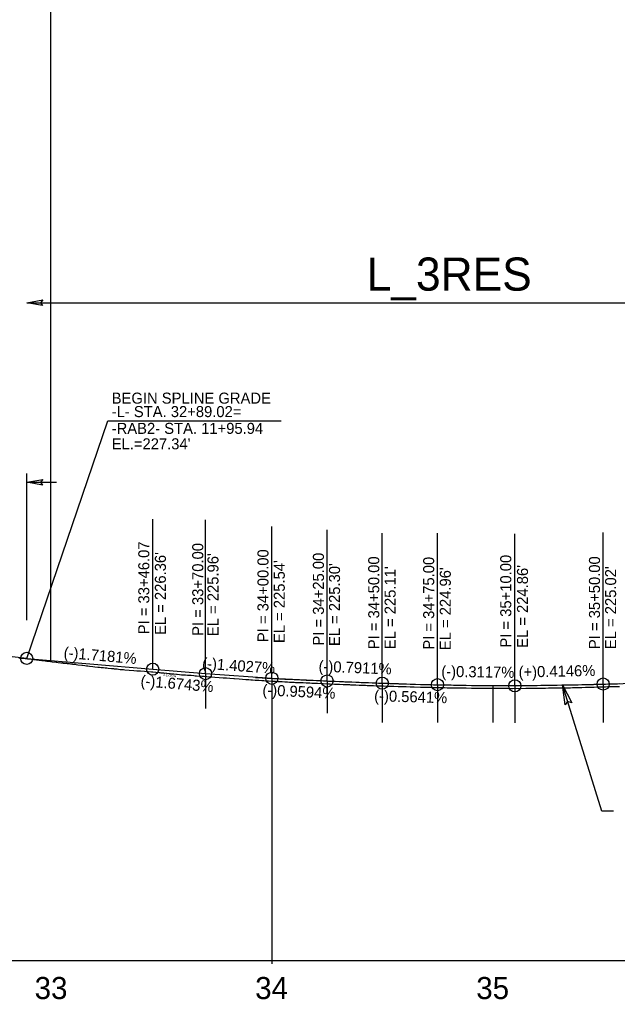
# Model space of a CAD drawing. Extents: x 2115752 to 2121174, y 562881 to 567245.
# Drawn here: x 2118982.1 to 2119252.8, y 566358.2 to 566801.7 of the extents above; entities that cross this region are included whole.
import ezdxf

# ---------------------------------------------------------------- set-up
doc = ezdxf.new("R2010")
doc.units = 0
for name, color, linetype in [('Exist Profile Cell', 7, 'Continuous'), ('Exist Vertical Profile Ground Line', 7, 'Continuous'), ('Exist Vertical Profile Horizontal Axis Label Major', 7, 'Continuous'), ('Prop Terminator CELL', 7, 'Continuous'), ('Prop Vertical Profile Grade', 7, 'Continuous'), ('Prop Vertical Profile Grade Label', 7, 'Continuous'), ('Prop VPI Label', 7, 'Continuous'), ('Scratch_Level_1', 7, 'Continuous')]:
    doc.layers.add(name, color=color, linetype=linetype)

msp = doc.modelspace()

# ---------------------------------------------------------------- linework, layer by layer
at = {"layer": 'Exist Profile Cell'}
msp.add_line((2116696.3, 566375.81), (2121174.42, 566375.81), dxfattribs=at)
at = {"layer": 'Exist Vertical Profile Ground Line'}
for points in [[(2118981.81, 566512.81), (2118982.8, 566512.69), (2118983.58, 566512.6), (2118985.71, 566512.32), (2118987.44, 566512.13), (2118988.58, 566512), (2118989.01, 566511.95), (2118989.75, 566511.87), (2118992.13, 566511.6), (2118992.91, 566511.51), (2118994.39, 566511.32), (2118995.37, 566511.2), (2118996.03, 566511.13), (2118996.87, 566511.01), (2118998.63, 566510.81), (2118999.03, 566510.77), (2118999.56, 566510.72), (2119000.8, 566510.55), (2119001.4, 566510.48), (2119001.88, 566510.42), (2119003.15, 566510.29), (2119003.67, 566510.22), (2119005.12, 566510.04), (2119005.99, 566509.95), (2119006.75, 566509.87), (2119008.48, 566509.64), (2119010.25, 566509.46), (2119010.63, 566509.41), (2119011.65, 566509.28), (2119012.46, 566509.19), (2119012.95, 566509.14), (2119013.77, 566509.05), (2119015.27, 566508.88), (2119016.22, 566508.77), (2119017.59, 566508.62), (2119018.3, 566508.54), (2119019.09, 566508.46), (2119020.05, 566508.35), (2119020.92, 566508.26), (2119021.65, 566508.18), (2119022.23, 566508.12), (2119023.76, 566507.96), (2119024.55, 566507.88), (2119024.98, 566507.83), (2119026.21, 566507.73), (2119026.87, 566507.64), (2119027.58, 566507.56), (2119027.94, 566507.52), (2119028.28, 566507.49), (2119029.19, 566507.43), (2119029.7, 566507.4), (2119031.71, 566507.18), (2119033.83, 566507.02), (2119035.12, 566506.93), (2119036.78, 566506.87), (2119038.69, 566506.67), (2119040.37, 566506.57), (2119041.83, 566506.42), (2119042.4, 566506.37), (2119043.85, 566506.27), (2119045.25, 566506.13), (2119045.63, 566506.11), (2119046.06, 566506.06), (2119047.45, 566505.97), (2119048.64, 566505.84), (2119049.82, 566505.72), (2119050.92, 566505.6), (2119051.98, 566505.48), (2119053.45, 566505.33), (2119054.47, 566505.22), (2119055.43, 566505.15), (2119056.27, 566505.11), (2119057.2, 566505.01), (2119058.09, 566504.93), (2119058.82, 566504.9), (2119059.84, 566504.86), (2119060.94, 566504.75), (2119061.6, 566504.69), (2119062.16, 566504.66), (2119064.56, 566504.49), (2119064.97, 566504.46), (2119065.61, 566504.41), (2119066.86, 566504.34), (2119068.24, 566504.21), (2119068.98, 566504.14), (2119070.44, 566504.05), (2119072.44, 566503.9), (2119074.27, 566503.73), (2119075.8, 566503.65), (2119077.25, 566503.51), (2119079.1, 566503.42), (2119079.41, 566503.4), (2119081.57, 566503.23), (2119083.05, 566503.14), (2119084.51, 566503.02), (2119085.92, 566502.93), (2119086.75, 566502.87), (2119087.51, 566502.79), (2119088.83, 566502.69)], [(2119088.83, 566502.69), (2119089.33, 566502.67), (2119089.88, 566502.64), (2119090.48, 566502.6), (2119091.81, 566502.49), (2119092.72, 566502.45), (2119093.42, 566502.4), (2119094.2, 566502.37), (2119094.83, 566502.33), (2119096.12, 566502.28), (2119096.96, 566502.22), (2119097.89, 566502.18), (2119099.1, 566502.1), (2119099.71, 566502.05), (2119101.05, 566502), (2119102.14, 566501.94), (2119103.37, 566501.88), (2119104.37, 566501.81), (2119105.22, 566501.8), (2119106.37, 566501.74), (2119107.07, 566501.68), (2119108.49, 566501.66), (2119109.36, 566501.62), (2119110.46, 566501.57), (2119111.81, 566501.47), (2119112.52, 566501.47), (2119113.55, 566501.43), (2119114.45, 566501.37), (2119116.5, 566501.31), (2119117.05, 566501.26), (2119119.57, 566501.15), (2119121.91, 566501.04), (2119122.74, 566501.01), (2119124.67, 566500.93), (2119126.92, 566500.83), (2119128.64, 566500.76), (2119129.34, 566500.72), (2119129.72, 566500.71), (2119131.46, 566500.64), (2119131.94, 566500.62), (2119132.54, 566500.6), (2119134.3, 566500.52), (2119135.83, 566500.47), (2119136.72, 566500.43), (2119137.13, 566500.41), (2119138.73, 566500.34), (2119139.39, 566500.31), (2119139.99, 566500.29), (2119141.63, 566500.23), (2119142.34, 566500.21), (2119143.57, 566500.17), (2119144.49, 566500.13), (2119146.08, 566500.09), (2119146.53, 566500.07), (2119146.9, 566500.06), (2119148.63, 566500), (2119149.72, 566499.97), (2119150.34, 566499.95), (2119151.53, 566499.9), (2119153.45, 566499.84), (2119153.75, 566499.83), (2119155.93, 566499.75), (2119157.19, 566499.73), (2119158.86, 566499.67), (2119160.4, 566499.62), (2119160.79, 566499.61), (2119163.65, 566499.53), (2119164.12, 566499.52), (2119164.5, 566499.51), (2119167.36, 566499.45), (2119168.22, 566499.43), (2119169.55, 566499.38), (2119170.7, 566499.37), (2119171.3, 566499.36), (2119171.96, 566499.35), (2119173.08, 566499.32), (2119174.08, 566499.31), (2119174.51, 566499.3), (2119175.68, 566499.27), (2119177.46, 566499.24), (2119178.49, 566499.23), (2119179.34, 566499.22), (2119180.13, 566499.19), (2119180.85, 566499.18), (2119181.67, 566499.17), (2119183.06, 566499.15), (2119184.23, 566499.13), (2119186.72, 566499.07), (2119187.59, 566499.05), (2119188.97, 566499.05), (2119190.38, 566499.03), (2119190.99, 566499.03), (2119192.53, 566499.05), (2119194.1, 566499.01), (2119194.43, 566499), (2119196.05, 566499), (2119197.82, 566498.98), (2119198.38, 566498.99), (2119199.59, 566499.02), (2119201.58, 566498.99), (2119203.14, 566499)], [(2119203.14, 566499), (2119204.77, 566498.97), (2119205.29, 566498.96), (2119206.66, 566498.98), (2119207.98, 566498.96), (2119208.54, 566498.97), (2119209.01, 566498.96), (2119211.33, 566498.98), (2119211.97, 566499), (2119212.71, 566499.01), (2119214.66, 566499.02), (2119215.51, 566499.03), (2119216.41, 566499.05), (2119218.15, 566499.09), (2119219.07, 566499.09), (2119220.14, 566499.12), (2119221.49, 566499.14), (2119222.56, 566499.15), (2119223.93, 566499.18), (2119224.44, 566499.19), (2119224.85, 566499.2), (2119225.57, 566499.21), (2119227.55, 566499.25), (2119227.9, 566499.25), (2119228.2, 566499.25), (2119231.15, 566499.26), (2119231.59, 566499.27), (2119232.36, 566499.29), (2119233.27, 566499.31), (2119234.96, 566499.36), (2119236.7, 566499.4), (2119238.31, 566499.43), (2119238.84, 566499.44), (2119239.16, 566499.45), (2119241.98, 566499.53), (2119242.29, 566499.54), (2119243.87, 566499.58), (2119245.11, 566499.62), (2119246.17, 566499.66), (2119247.34, 566499.68), (2119248.48, 566499.73), (2119250.02, 566499.77), (2119251.76, 566499.81), (2119252.75, 566499.83), (2119253.65, 566499.85)]]:
    msp.add_lwpolyline(points, dxfattribs=at)
at = {"layer": 'Prop Terminator CELL'}
for points in [[(2118992.52, 566591.01), (2118985.32, 566592.25), (2118992.56, 566593.53), (2118991.64, 566592.25)], [(2119229.06, 566491.47), (2119227.85, 566500.53), (2119232.08, 566492.37), (2119230.21, 566492.99)]]:
    msp.add_lwpolyline(points, close=True, dxfattribs=at)
at = {"layer": 'Prop Vertical Profile Grade'}
msp.add_lwpolyline([(2118985.32, 566512.53), (2119042.37, 566507.63), (2119066.3, 566505.62), (2119096.3, 566503.52), (2119121.3, 566502.32), (2119146.3, 566501.33), (2119171.3, 566500.63), (2119206.3, 566500.08), (2119246.3, 566500.91), (2119296.3, 566502.56), (2119321.3, 566503.63), (2119356.3, 566505.99)], dxfattribs=at)
at = {"layer": 'Prop VPI Label'}
for p, q in [((2118985.32, 566512.53), (2119022.04, 566620.13)), ((2119022.04, 566620.13), (2119100.59, 566620.13)), ((2118985.32, 566529.85), (2118985.32, 566596.16)), ((2118985.32, 566592.25), (2118998.8, 566592.25)), ((2119042.37, 566507.63), (2119042.37, 566575.61)), ((2119066.3, 566505.62), (2119066.3, 566575.18)), ((2119096.3, 566503.52), (2119096.3, 566572.16)), ((2119121.3, 566502.32), (2119121.3, 566570.65)), ((2119146.3, 566501.33), (2119146.3, 566569.14)), ((2119171.3, 566500.63), (2119171.3, 566569.14)), ((2119206.3, 566500.08), (2119206.3, 566568.92)), ((2119246.3, 566500.91), (2119246.3, 566569.53)), ((2118985.32, 566512.53), (2118966.65, 566514.53))]:
    msp.add_line(p, q, dxfattribs=at)
msp.add_lwpolyline([(2119251.04, 566443.36), (2119245.74, 566443.36), (2119227.85, 566500.53)], dxfattribs=at)
for centre in [(2118985.32, 566512.53), (2119042.37, 566507.63), (2119066.3, 566505.62), (2119096.3, 566503.52), (2119121.3, 566502.32), (2119146.3, 566501.33), (2119171.3, 566500.63), (2119246.3, 566500.91), (2119206.3, 566500.08)]:
    msp.add_circle(centre, 2.75, dxfattribs=at)
at = {"layer": 'Scratch_Level_1'}
for p, q in [((2118996.3, 566511.09), (2118996.3, 567245.2)), ((2118985.32, 566673.51), (2119356.3, 566673.51)), ((2118985.32, 566512.38), (2118985.32, 566512.53)), ((2118985.32, 566512.53), (2118996.3, 566511.09)), ((2119047.45, 566505.97), (2119054.47, 566505.22)), ((2119066.3, 566505.62), (2119066.3, 566489.88)), ((2119096.3, 566503.52), (2119096.3, 566374.25)), ((2119121.3, 566502.32), (2119121.3, 566487.77)), ((2119146.3, 566501.33), (2119146.3, 566483.58)), ((2119171.3, 566500.63), (2119171.3, 566483.58)), ((2119196.3, 566500.25), (2119196.3, 566483.55)), ((2119206.3, 566500.22), (2119206.3, 566483.37)), ((2119246.3, 566500.91), (2119246.3, 566483.58))]:
    msp.add_line(p, q, dxfattribs=at)
msp.add_lwpolyline([(2118992.52, 566672.27), (2118985.32, 566673.51), (2118992.56, 566674.79), (2118991.64, 566673.51)], close=True, dxfattribs=at)
for points in [[(2119000.34, 566510.61), (2119007.79, 566509.97)], [(2119088.88, 566503.94), (2119089.4, 566503.92), (2119089.96, 566503.88), (2119090.57, 566503.85), (2119091.9, 566503.74), (2119092.79, 566503.69), (2119093.48, 566503.65), (2119094.26, 566503.62), (2119094.89, 566503.58), (2119096.19, 566503.53), (2119097.03, 566503.47), (2119097.96, 566503.42), (2119099.19, 566503.35), (2119099.78, 566503.3), (2119101.11, 566503.25), (2119102.2, 566503.18), (2119103.44, 566503.13), (2119104.42, 566503.06), (2119105.26, 566503.05), (2119106.46, 566502.99), (2119107.14, 566502.93), (2119108.53, 566502.91), (2119109.42, 566502.87), (2119110.53, 566502.81), (2119111.85, 566502.72), (2119112.54, 566502.73), (2119113.62, 566502.68), (2119114.51, 566502.62), (2119116.57, 566502.56), (2119117.14, 566502.51), (2119119.63, 566502.4), (2119121.96, 566502.29), (2119122.79, 566502.26), (2119124.73, 566502.18), (2119126.98, 566502.07), (2119128.69, 566502.01), (2119129.4, 566501.97), (2119129.77, 566501.96), (2119131.5, 566501.89), (2119132, 566501.87), (2119132.59, 566501.85), (2119134.35, 566501.77), (2119135.88, 566501.72), (2119136.78, 566501.68), (2119137.18, 566501.66), (2119138.79, 566501.59), (2119139.44, 566501.56), (2119140.04, 566501.54), (2119141.67, 566501.48), (2119142.38, 566501.46), (2119143.61, 566501.42), (2119144.54, 566501.38), (2119146.12, 566501.34), (2119146.57, 566501.32), (2119146.94, 566501.31), (2119148.67, 566501.25), (2119149.76, 566501.22), (2119150.39, 566501.2), (2119151.58, 566501.15), (2119153.49, 566501.09), (2119153.79, 566501.08), (2119155.96, 566501), (2119157.22, 566500.98), (2119158.9, 566500.92), (2119160.44, 566500.87), (2119160.83, 566500.85), (2119163.68, 566500.78), (2119164.16, 566500.77), (2119164.54, 566500.76), (2119167.39, 566500.7), (2119168.26, 566500.68), (2119169.57, 566500.63), (2119170.72, 566500.62), (2119171.32, 566500.61), (2119171.99, 566500.6), (2119173.11, 566500.57), (2119174.1, 566500.56), (2119174.53, 566500.55), (2119175.71, 566500.52), (2119177.47, 566500.49), (2119178.51, 566500.48), (2119179.37, 566500.47), (2119180.16, 566500.44), (2119180.87, 566500.43), (2119181.69, 566500.42), (2119183.08, 566500.4), (2119184.26, 566500.38), (2119186.75, 566500.32), (2119187.6, 566500.3), (2119188.98, 566500.3), (2119190.39, 566500.28), (2119190.99, 566500.28), (2119192.54, 566500.3), (2119194.12, 566500.26), (2119194.43, 566500.25), (2119196.06, 566500.25), (2119197.82, 566500.23), (2119198.35, 566500.24), (2119199.58, 566500.27), (2119201.58, 566500.24), (2119203.14, 566500.25)], [(2119203.16, 566500.25), (2119204.79, 566500.22), (2119205.29, 566500.21), (2119206.66, 566500.23), (2119207.98, 566500.21), (2119208.54, 566500.22), (2119209.02, 566500.21), (2119211.31, 566500.23), (2119211.95, 566500.25), (2119212.7, 566500.26), (2119214.65, 566500.27), (2119215.49, 566500.28), (2119216.39, 566500.3), (2119218.14, 566500.34), (2119219.05, 566500.34), (2119220.12, 566500.37), (2119221.47, 566500.39), (2119222.54, 566500.4), (2119223.91, 566500.43), (2119224.42, 566500.44), (2119224.83, 566500.45), (2119225.54, 566500.46), (2119227.53, 566500.5), (2119227.88, 566500.5), (2119228.2, 566500.5), (2119231.14, 566500.51), (2119231.56, 566500.52), (2119232.34, 566500.54), (2119233.24, 566500.56), (2119234.92, 566500.61), (2119236.67, 566500.65), (2119238.29, 566500.68), (2119238.81, 566500.69), (2119239.13, 566500.7), (2119241.94, 566500.78), (2119242.25, 566500.79), (2119243.83, 566500.83), (2119245.07, 566500.87), (2119246.14, 566500.91), (2119247.3, 566500.93), (2119248.44, 566500.98), (2119249.99, 566501.02), (2119251.74, 566501.06), (2119252.73, 566501.08), (2119253.62, 566501.1)]]:
    msp.add_lwpolyline(points, dxfattribs=at)

# ---------------------------------------------------------------- texts
at = {"layer": 'Exist Vertical Profile Horizontal Axis Label Major'}
for s, p in [('33', (2118988.91, 566358.31)), ('34', (2119088.76, 566358.31)), ('35', (2119188.85, 566358.31))]:
    msp.add_text(s, height=10, dxfattribs=at).set_placement(p)
at = {"layer": 'Prop Vertical Profile Grade Label'}
for s, rotation, p in [('(-)1.7181%', 355.0899, (2119001.91, 566512.78)), ('(-)1.4027%', 355.9882, (2119064.64, 566507.88)), ('(-)0.7911%', 357.7349, (2119117.39, 566506.54)), ('(-)0.3117%', 359.1072, (2119173, 566504.2)), ('(+)0.4146%', 1.1877, (2119208.07, 566503.86)), ('(-)1.6743%', 355.2146, (2119036.74, 566499.98)), ('(-)0.9594%', 357.2537, (2119091.96, 566495.82)), ('(-)0.5641%', 358.3843, (2119142.57, 566493.15))]:
    msp.add_text(s, height=5, rotation=rotation, dxfattribs=at).set_placement(p)
at = {"layer": 'Prop VPI Label'}
for s, p in [('BEGIN SPLINE GRADE', (2119023.81, 566627.83)), ('-L- STA. 32+89.02=', (2119023.81, 566621.74)), ('-RAB2- STA. 11+95.94', (2119023.81, 566614.15)), ("EL.=227.34'", (2119023.81, 566607.15))]:
    msp.add_text(s, height=5, dxfattribs=at).set_placement(p)
for s, p in [('PI = 33+46.07', (2119040.84, 566523.44)), ('PI = 33+70.00', (2119065.27, 566522.74)), ('PI = 34+00.00', (2119094.79, 566519.9)), ("EL = 226.36'", (2119048.34, 566523.13)), ("EL = 225.96'", (2119072.16, 566522.62)), ("EL = 225.54'", (2119102.18, 566519.46)), ('PI = 34+25.00', (2119119.89, 566518.34)), ('PI = 34+50.00', (2119144.94, 566516.69)), ('PI = 34+75.00', (2119169.81, 566516.48)), ('PI = 35+10.00', (2119204.71, 566517.4)), ('PI = 35+50.00', (2119244.88, 566516.73)), ("EL = 225.30'", (2119127.18, 566518.1)), ("EL = 225.11'", (2119152.35, 566516.7)), ("EL = 224.96'", (2119177.34, 566516.24)), ("EL = 224.86'", (2119212.28, 566517.28)), ("EL = 225.02'", (2119252.19, 566516.71))]:
    msp.add_text(s, height=5, rotation=90, dxfattribs=at).set_placement(p)
at = {"layer": 'Scratch_Level_1'}
msp.add_text('L_3RES', height=15, dxfattribs=at).set_placement((2119139.25, 566678.98))
msp.add_text('-2.1539 %', height=1, rotation=353.8532, dxfattribs=at).set_placement((2119046.68, 566504.65))

doc.saveas('drawing.dxf')
